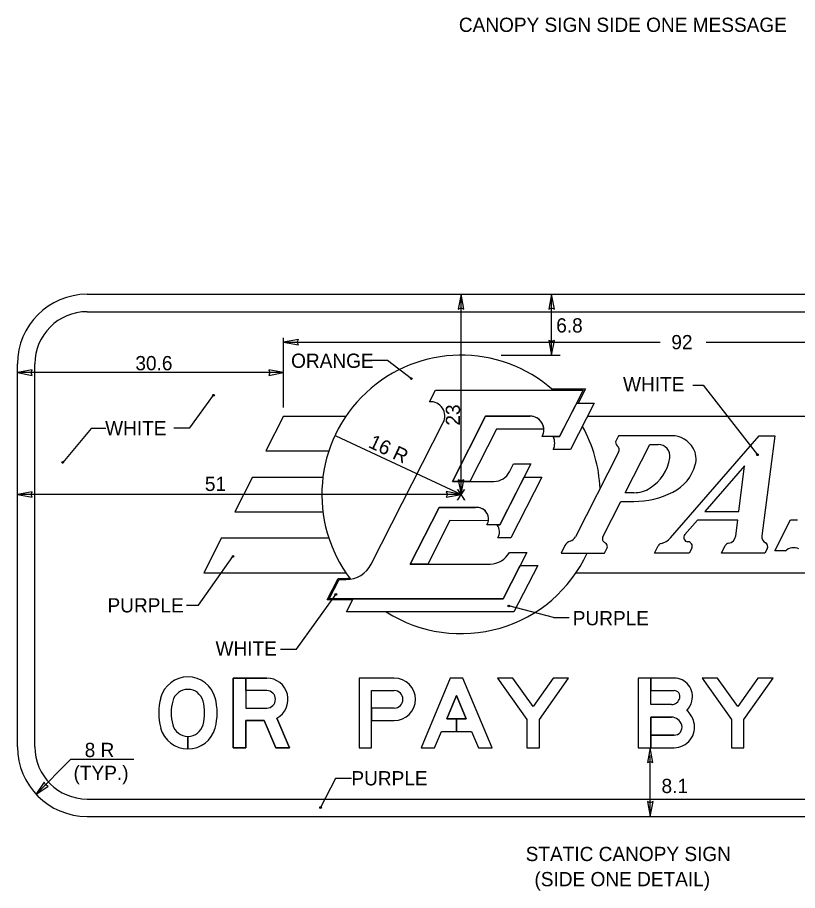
# Model space of a CAD drawing. Extents: x 319706 to 320449, y 1621775 to 1622117.
# Drawn here: x 319821.8 to 319898.5, y 1621852.1 to 1621937.8 of the extents above; entities that cross this region are included whole.
import ezdxf

# ---------------------------------------------------------------- set-up
doc = ezdxf.new("R2010")
doc.units = 0
for name, color, linetype in [('1', 7, 'Continuous'), ('52', 7, 'Continuous'), ('GSBWFill', 7, 'Continuous'), ('GSColorFill', 7, 'Continuous'), ('GSOutline', 7, 'Continuous'), ('SignPanel', 7, 'Continuous')]:
    doc.layers.add(name, color=color, linetype=linetype)

msp = doc.modelspace()

# ---------------------------------------------------------------- linework, layer by layer
at = {"layer": '1'}
for p, q in [((319865.435, 1621890.975), (319865.435, 1621910.64)), ((319874.341, 1621904.654), (319874.341, 1621910.639)), ((319847.993, 1621899.525), (319847.993, 1621906.365)), ((319847.993, 1621905.938), (319884.997, 1621905.938)), ((319889.548, 1621905.938), (319926.653, 1621905.938)), ((319856.646, 1621904.176), (319858.193, 1621904.176)), ((319858.193, 1621904.176), (319860.552, 1621902.355)), ((319869.368, 1621904.654), (319875.196, 1621904.654)), ((319847.993, 1621902.945), (319821.83, 1621902.945)), ((319888.22, 1621901.716), (319889.238, 1621901.716)), ((319889.238, 1621901.716), (319894.572, 1621894.876)), ((319838.762, 1621897.524), (319841.1, 1621900.723)), ((319829.062, 1621897.454), (319826.277, 1621894.117)), ((319830.508, 1621897.454), (319829.062, 1621897.454)), ((319837.215, 1621897.524), (319838.762, 1621897.524)), ((319865.435, 1621890.974), (319853.158, 1621896.699)), ((319850.398, 1621890.975), (319821.83, 1621890.975)), ((319865.435, 1621890.975), (319850.398, 1621890.975)), ((319839.622, 1621880.096), (319843.019, 1621884.886)), ((319849.249, 1621875.759), (319853.128, 1621881.149)), ((319838.436, 1621880.096), (319839.622, 1621880.096)), ((319874.522, 1621878.868), (319870.131, 1621880.017)), ((319874.522, 1621878.868), (319876.07, 1621878.868)), ((319847.701, 1621875.759), (319849.249, 1621875.759)), ((319823.628, 1621861.492), (319827.091, 1621864.955)), ((319827.091, 1621864.955), (319833.282, 1621864.955)), ((319884.034, 1621859.339), (319884.034, 1621865.324)), ((319853.1, 1621863.057), (319851.628, 1621860.204)), ((319854.662, 1621863.057), (319853.1, 1621863.057))]:
    msp.add_line(p, q, dxfattribs=at)
for centre in [(319860.552, 1621902.354), (319841.1, 1621900.722), (319894.571, 1621894.875), (319826.277, 1621894.116), (319843.019, 1621884.884), (319853.128, 1621881.148), (319870.131, 1621880.015), (319870.131, 1621880.015), (319851.628, 1621860.204)]:
    msp.add_circle(centre, 0.0855, dxfattribs=at)
at = {"layer": '52'}
for p, q in [((319865.435, 1621910.64), (319865.155, 1621909.19)), ((319865.705, 1621909.19), (319865.435, 1621910.64)), ((319874.341, 1621910.639), (319874.061, 1621909.189)), ((319874.611, 1621909.189), (319874.341, 1621910.639)), ((319865.155, 1621909.19), (319865.435, 1621909.3)), ((319865.435, 1621909.3), (319865.705, 1621909.19)), ((319874.061, 1621909.189), (319874.341, 1621909.299)), ((319874.341, 1621909.299), (319874.611, 1621909.189)), ((319849.443, 1621906.208), (319847.993, 1621905.938)), ((319847.993, 1621905.938), (319849.443, 1621905.658)), ((319849.333, 1621905.938), (319849.443, 1621906.208)), ((319849.443, 1621905.658), (319849.333, 1621905.938)), ((319874.341, 1621905.994), (319874.071, 1621906.104)), ((319874.071, 1621906.104), (319874.341, 1621904.654)), ((319874.341, 1621904.654), (319874.621, 1621906.104)), ((319874.621, 1621906.104), (319874.341, 1621905.994)), ((319823.28, 1621903.215), (319821.83, 1621902.945)), ((319823.17, 1621902.945), (319823.28, 1621903.215)), ((319847.993, 1621902.945), (319846.543, 1621903.225)), ((319846.543, 1621903.225), (319846.653, 1621902.945)), ((319821.83, 1621902.945), (319823.28, 1621902.665)), ((319823.28, 1621902.665), (319823.17, 1621902.945)), ((319846.653, 1621902.945), (319846.543, 1621902.675)), ((319846.543, 1621902.675), (319847.993, 1621902.945)), ((319865.435, 1621892.315), (319865.165, 1621892.425)), ((319865.165, 1621892.425), (319865.435, 1621890.975)), ((319865.435, 1621890.975), (319865.715, 1621892.425)), ((319865.715, 1621892.425), (319865.435, 1621892.315)), ((319823.28, 1621891.245), (319821.83, 1621890.975)), ((319823.17, 1621890.975), (319823.28, 1621891.245)), ((319865.435, 1621890.975), (319863.985, 1621891.255)), ((319863.985, 1621891.255), (319864.095, 1621890.975)), ((319821.83, 1621890.975), (319823.28, 1621890.695)), ((319823.28, 1621890.695), (319823.17, 1621890.975)), ((319864.095, 1621890.975), (319863.985, 1621890.705)), ((319863.985, 1621890.705), (319865.435, 1621890.975)), ((319884.034, 1621866.088), (319883.754, 1621864.638)), ((319884.304, 1621864.638), (319884.034, 1621866.088)), ((319883.754, 1621864.638), (319884.034, 1621864.748)), ((319884.034, 1621864.748), (319884.304, 1621864.638)), ((319824.463, 1621862.708), (319823.628, 1621861.492)), ((319823.628, 1621861.492), (319824.851, 1621862.32)), ((319824.576, 1621862.44), (319824.463, 1621862.708)), ((319824.851, 1621862.32), (319824.576, 1621862.44)), ((319884.034, 1621860.679), (319883.764, 1621860.789)), ((319883.764, 1621860.789), (319884.034, 1621859.339)), ((319884.034, 1621859.339), (319884.314, 1621860.789)), ((319884.314, 1621860.789), (319884.034, 1621860.679))]:
    msp.add_line(p, q, dxfattribs=at)
at = {"layer": 'GSBWFill'}
for p, q in [((319856.649, 1621871.698), (319858.873, 1621871.698)), ((319838.587, 1621867.199), (319838.587, 1621865.968)), ((319838.588, 1621865.968), (319838.588, 1621867.199))]:
    msp.add_line(p, q, dxfattribs=at)
for points in [[(319847.316, 1621868.997), (319848.576, 1621866.088), (319847.234, 1621866.088), (319846.079, 1621868.756), (319844.266, 1621868.756), (319844.266, 1621866.088), (319843.034, 1621866.088), (319843.034, 1621872.929), (319844.266, 1621872.929), (319844.266, 1621869.987), (319846.342, 1621869.987)], [(319844.266, 1621871.698), (319844.266, 1621872.929), (319846.342, 1621872.929)], [(319858.873, 1621872.929), (319855.418, 1621872.929), (319855.418, 1621866.088), (319856.649, 1621866.088), (319856.649, 1621871.698)], [(319886.111, 1621870.329), (319884.084, 1621870.329), (319884.084, 1621872.929), (319882.852, 1621872.929), (319882.852, 1621866.088), (319884.084, 1621866.088)], [(319886.376, 1621872.929), (319884.084, 1621872.929), (319884.084, 1621871.698), (319886.376, 1621871.698)], [(319846.342, 1621871.698), (319844.266, 1621871.698)], [(319858.873, 1621869.987), (319856.649, 1621869.987), (319856.649, 1621868.756), (319858.873, 1621868.756)], [(319884.084, 1621866.088), (319884.084, 1621869.098), (319886.111, 1621869.098)], [(319886.376, 1621867.319), (319884.084, 1621867.319), (319884.084, 1621866.088), (319886.376, 1621866.088)]]:
    msp.add_lwpolyline(points, dxfattribs=at)
for points in [[(319865.957, 1621868.927), (319864.996, 1621868.927), (319864.996, 1621867.695), (319866.474, 1621867.695), (319867.149, 1621866.088), (319868.485, 1621866.088), (319865.612, 1621872.929), (319864.38, 1621872.929), (319861.507, 1621866.088), (319862.842, 1621866.088), (319863.518, 1621867.695), (319864.996, 1621867.695), (319864.996, 1621868.927), (319864.035, 1621868.927), (319864.996, 1621871.215)], [(319873.137, 1621868.858), (319876.011, 1621872.929), (319874.503, 1621872.929), (319872.522, 1621870.122), (319870.54, 1621872.929), (319869.032, 1621872.929), (319871.906, 1621868.858), (319871.906, 1621866.088), (319873.137, 1621866.088)], [(319893.251, 1621868.858), (319896.125, 1621872.929), (319894.618, 1621872.929), (319892.636, 1621870.122), (319890.654, 1621872.929), (319889.147, 1621872.929), (319892.02, 1621868.858), (319892.02, 1621866.088), (319893.251, 1621866.088)]]:
    msp.add_lwpolyline(points, close=True, dxfattribs=at)
for centre, radius, start, end in [((319838.587, 1621870.276), 2.773, 14.96177, 165.03823), ((319846.342, 1621870.843), 2.087, 297.837, 90), ((319886.376, 1621871.116), 1.813, 345.52249, 90), ((319838.587, 1621870.276), 1.541, 14.96177, 165.03823), ((319846.342, 1621870.843), 0.855, 270, 90), ((319886.376, 1621871.116), 0.582, 345.52249, 90), ((319841.461, 1621869.508), 5.747, 165.03823, 194.96177), ((319841.461, 1621869.508), 4.515, 165.03823, 194.96177), ((319835.714, 1621869.508), 4.515, 345.03823, 14.96177), ((319835.714, 1621869.508), 5.747, 345.03823, 14.96177), ((319886.111, 1621871.185), 0.855, 270, 345.52249), ((319886.111, 1621871.185), 2.087, 316.7114, 345.52249), ((319886.111, 1621868.037), 2.292, 14.47751, 48.4921), ((319886.111, 1621868.037), 1.06, 14.47751, 90), ((319838.587, 1621868.741), 2.773, 194.96177, 270), ((319838.587, 1621868.741), 1.541, 194.96177, 270), ((319838.587, 1621868.741), 1.541, 270.01272, 345.03823), ((319838.587, 1621868.741), 2.773, 270.00707, 345.03823), ((319886.376, 1621868.106), 2.018, 270, 14.47751), ((319886.376, 1621868.106), 0.787, 270, 14.47751)]:
    msp.add_arc(centre, radius, start, end, dxfattribs=at)
for major_axis in [(0, 2.087), (0, 0.855)]:
    msp.add_ellipse((319858.873, 1621870.843), major_axis=major_axis, ratio=0.999994, start_param=3.141593, end_param=6.283185, dxfattribs=at)
at = {"layer": 'GSColorFill'}
for p, q in [((319856.649, 1621871.698), (319858.873, 1621871.698)), ((319838.587, 1621867.199), (319838.587, 1621865.968)), ((319838.588, 1621865.968), (319838.588, 1621867.199))]:
    msp.add_line(p, q, dxfattribs=at)
for points in [[(319847.316, 1621868.997), (319848.576, 1621866.088), (319847.234, 1621866.088), (319846.079, 1621868.756), (319844.266, 1621868.756), (319844.266, 1621866.088), (319843.034, 1621866.088), (319843.034, 1621872.929), (319844.266, 1621872.929), (319844.266, 1621869.987), (319846.342, 1621869.987)], [(319844.266, 1621871.698), (319844.266, 1621872.929), (319846.342, 1621872.929)], [(319858.873, 1621872.929), (319855.418, 1621872.929), (319855.418, 1621866.088), (319856.649, 1621866.088), (319856.649, 1621871.698)], [(319886.111, 1621870.329), (319884.084, 1621870.329), (319884.084, 1621872.929), (319882.852, 1621872.929), (319882.852, 1621866.088), (319884.084, 1621866.088)], [(319886.376, 1621872.929), (319884.084, 1621872.929), (319884.084, 1621871.698), (319886.376, 1621871.698)], [(319846.342, 1621871.698), (319844.266, 1621871.698)], [(319858.873, 1621869.987), (319856.649, 1621869.987), (319856.649, 1621868.756), (319858.873, 1621868.756)], [(319884.084, 1621866.088), (319884.084, 1621869.098), (319886.111, 1621869.098)], [(319886.376, 1621867.319), (319884.084, 1621867.319), (319884.084, 1621866.088), (319886.376, 1621866.088)]]:
    msp.add_lwpolyline(points, dxfattribs=at)
for points in [[(319865.957, 1621868.927), (319864.996, 1621868.927), (319864.996, 1621867.695), (319866.474, 1621867.695), (319867.149, 1621866.088), (319868.485, 1621866.088), (319865.612, 1621872.929), (319864.38, 1621872.929), (319861.507, 1621866.088), (319862.842, 1621866.088), (319863.518, 1621867.695), (319864.996, 1621867.695), (319864.996, 1621868.927), (319864.035, 1621868.927), (319864.996, 1621871.215)], [(319873.137, 1621868.858), (319876.011, 1621872.929), (319874.503, 1621872.929), (319872.522, 1621870.122), (319870.54, 1621872.929), (319869.032, 1621872.929), (319871.906, 1621868.858), (319871.906, 1621866.088), (319873.137, 1621866.088)], [(319893.251, 1621868.858), (319896.125, 1621872.929), (319894.618, 1621872.929), (319892.636, 1621870.122), (319890.654, 1621872.929), (319889.147, 1621872.929), (319892.02, 1621868.858), (319892.02, 1621866.088), (319893.251, 1621866.088)]]:
    msp.add_lwpolyline(points, close=True, dxfattribs=at)
for centre, radius, start, end in [((319838.587, 1621870.276), 2.773, 14.96177, 165.03823), ((319846.342, 1621870.843), 2.087, 297.837, 90), ((319886.376, 1621871.116), 1.813, 345.52249, 90), ((319838.587, 1621870.276), 1.541, 14.96177, 165.03823), ((319846.342, 1621870.843), 0.855, 270, 90), ((319886.376, 1621871.116), 0.582, 345.52249, 90), ((319841.461, 1621869.508), 5.747, 165.03823, 194.96177), ((319841.461, 1621869.508), 4.515, 165.03823, 194.96177), ((319835.714, 1621869.508), 4.515, 345.03823, 14.96177), ((319835.714, 1621869.508), 5.747, 345.03823, 14.96177), ((319886.111, 1621871.185), 0.855, 270, 345.52249), ((319886.111, 1621871.185), 2.087, 316.7114, 345.52249), ((319886.111, 1621868.037), 2.292, 14.47751, 48.4921), ((319886.111, 1621868.037), 1.06, 14.47751, 90), ((319838.587, 1621868.741), 2.773, 194.96177, 270), ((319838.587, 1621868.741), 1.541, 194.96177, 270), ((319838.587, 1621868.741), 1.541, 270.01272, 345.03823), ((319838.587, 1621868.741), 2.773, 270.00707, 345.03823), ((319886.376, 1621868.106), 2.018, 270, 14.47751), ((319886.376, 1621868.106), 0.787, 270, 14.47751)]:
    msp.add_arc(centre, radius, start, end, dxfattribs=at)
for major_axis in [(0, 2.087), (0, 0.855)]:
    msp.add_ellipse((319858.873, 1621870.843), major_axis=major_axis, ratio=0.999994, start_param=3.141593, end_param=6.283185, dxfattribs=at)
at = {"layer": 'GSOutline'}
for p, q in [((319856.649, 1621871.698), (319858.873, 1621871.698)), ((319856.649, 1621868.756), (319858.873, 1621868.756)), ((319882.852, 1621866.088), (319886.376, 1621866.088))]:
    msp.add_line(p, q, dxfattribs=at)
for points in [[(319846.342, 1621872.929), (319843.034, 1621872.929), (319843.034, 1621866.088), (319844.266, 1621866.088), (319844.266, 1621868.756), (319846.079, 1621868.756), (319847.234, 1621866.088), (319848.576, 1621866.088), (319847.316, 1621868.997)], [(319858.873, 1621872.929), (319855.418, 1621872.929), (319855.418, 1621866.088), (319856.649, 1621866.088), (319856.649, 1621868.756)], [(319886.376, 1621872.929), (319882.852, 1621872.929), (319882.852, 1621866.088)], [(319846.342, 1621871.698), (319844.266, 1621871.698), (319844.266, 1621869.987), (319846.342, 1621869.987)], [(319858.873, 1621869.987), (319856.649, 1621869.987), (319856.649, 1621871.698)], [(319886.111, 1621870.329), (319884.084, 1621870.329), (319884.084, 1621871.698), (319886.376, 1621871.698)], [(319886.111, 1621869.098), (319884.084, 1621869.098), (319884.084, 1621867.319), (319886.376, 1621867.319)]]:
    msp.add_lwpolyline(points, dxfattribs=at)
for points in [[(319863.518, 1621867.695), (319866.474, 1621867.695), (319867.149, 1621866.088), (319868.485, 1621866.088), (319865.612, 1621872.929), (319864.38, 1621872.929), (319861.507, 1621866.088), (319862.842, 1621866.088)], [(319873.137, 1621868.858), (319876.011, 1621872.929), (319874.503, 1621872.929), (319872.522, 1621870.122), (319870.54, 1621872.929), (319869.032, 1621872.929), (319871.906, 1621868.858), (319871.906, 1621866.088), (319873.137, 1621866.088)], [(319893.251, 1621868.858), (319896.125, 1621872.929), (319894.618, 1621872.929), (319892.636, 1621870.122), (319890.654, 1621872.929), (319889.147, 1621872.929), (319892.02, 1621868.858), (319892.02, 1621866.088), (319893.251, 1621866.088)], [(319865.957, 1621868.927), (319864.996, 1621871.215), (319864.035, 1621868.927)]]:
    msp.add_lwpolyline(points, close=True, dxfattribs=at)
for centre, radius, start, end in [((319838.587, 1621870.276), 2.773, 14.96177, 165.03823), ((319846.342, 1621870.843), 2.087, 297.837, 90), ((319886.376, 1621871.116), 1.813, 345.52249, 90), ((319838.587, 1621870.276), 1.541, 14.96177, 165.03823), ((319846.342, 1621870.843), 0.855, 270, 90), ((319886.376, 1621871.116), 0.582, 345.52249, 90), ((319841.461, 1621869.508), 5.747, 165.03823, 194.96177), ((319841.461, 1621869.508), 4.515, 165.03823, 194.96177), ((319835.714, 1621869.508), 4.515, 345.03823, 14.96177), ((319835.714, 1621869.508), 5.747, 345.03823, 14.96177), ((319886.111, 1621871.185), 0.855, 270, 345.52249), ((319886.111, 1621871.185), 2.087, 316.7114, 345.52249), ((319886.111, 1621868.037), 2.292, 14.47751, 48.4921), ((319886.111, 1621868.037), 1.06, 14.47751, 90), ((319838.587, 1621868.741), 2.773, 194.96177, 345.03823), ((319838.587, 1621868.741), 1.541, 194.96177, 345.03823), ((319886.376, 1621868.106), 2.018, 270, 14.47751), ((319886.376, 1621868.106), 0.787, 270, 14.47751)]:
    msp.add_arc(centre, radius, start, end, dxfattribs=at)
for major_axis in [(0, 2.087), (0, 0.855)]:
    msp.add_ellipse((319858.873, 1621870.843), major_axis=major_axis, ratio=0.999994, start_param=3.141593, end_param=6.283185, dxfattribs=at)
at = {"layer": 'SignPanel'}
for p, q in [((319828.67, 1621910.639), (319938.11, 1621910.639)), ((319828.67, 1621908.929), (319938.11, 1621908.929)), ((319821.83, 1621866.179), (319821.83, 1621903.799)), ((319823.54, 1621866.179), (319823.54, 1621903.799)), ((319862.341, 1621900.087), (319862.924, 1621901.234)), ((319862.924, 1621901.234), (319877.459, 1621901.234)), ((319874.335, 1621901.362), (319877.668, 1621901.362)), ((319877.459, 1621901.234), (319875.131, 1621896.663)), ((319877.668, 1621901.362), (319876.949, 1621899.952)), ((319875.128, 1621896.658), (319876.807, 1621899.952)), ((319875.128, 1621896.658), (319876.807, 1621899.952)), ((319878.534, 1621899.952), (319876.204, 1621895.38)), ((319878.534, 1621899.952), (319876.204, 1621895.38)), ((319876.807, 1621899.952), (319878.534, 1621899.952)), ((319876.807, 1621899.952), (319878.534, 1621899.952)), ((319847.993, 1621898.669), (319846.252, 1621895.249)), ((319847.993, 1621898.669), (319854.124, 1621898.669)), ((319856.596, 1621884.112), (319863.692, 1621898.04)), ((319867.85, 1621898.669), (319864.583, 1621892.257)), ((319864.583, 1621892.257), (319867.85, 1621898.669)), ((319864.583, 1621892.257), (319867.85, 1621898.669)), ((319872.208, 1621898.669), (319867.85, 1621898.669)), ((319867.85, 1621898.669), (319872.208, 1621898.669)), ((319867.85, 1621898.669), (319872.208, 1621898.669)), ((319877.879, 1621898.669), (319926.653, 1621898.669)), ((319868.924, 1621897.387), (319866.31, 1621892.257)), ((319868.924, 1621897.387), (319866.31, 1621892.257)), ((319873.575, 1621897.387), (319868.924, 1621897.387)), ((319873.575, 1621897.387), (319868.924, 1621897.387)), ((319875.131, 1621896.663), (319873.42, 1621896.663)), ((319874.492, 1621896.658), (319875.128, 1621896.658)), ((319874.492, 1621896.658), (319875.128, 1621896.658)), ((319880.91, 1621896.745), (319880.677, 1621896.289)), ((319886.146, 1621896.745), (319880.91, 1621896.745)), ((319886.015, 1621886.704), (319894.746, 1621896.745)), ((319894.746, 1621896.745), (319896.285, 1621896.745)), ((319896.285, 1621896.745), (319895.005, 1621886.906)), ((319876.204, 1621895.38), (319874.494, 1621895.38)), ((319876.204, 1621895.38), (319874.494, 1621895.38)), ((319881.581, 1621891.145), (319884, 1621895.89)), ((319884, 1621895.89), (319884.824, 1621895.89)), ((319846.252, 1621895.249), (319852.44, 1621895.249)), ((319880.925, 1621895.129), (319876.691, 1621886.821)), ((319872.303, 1621893.967), (319869.254, 1621887.982)), ((319870.197, 1621893.19), (319870.593, 1621893.967)), ((319870.593, 1621893.967), (319872.303, 1621893.967)), ((319893.314, 1621893.796), (319889.411, 1621889.306)), ((319892.73, 1621889.306), (319893.314, 1621893.796)), ((319844.947, 1621892.684), (319843.206, 1621889.264)), ((319844.947, 1621892.684), (319851.861, 1621892.684)), ((319864.583, 1621892.257), (319868.674, 1621892.257)), ((319866.31, 1621892.257), (319864.583, 1621892.257)), ((319866.31, 1621892.257), (319864.583, 1621892.257)), ((319869.254, 1621887.982), (319871.65, 1621892.684)), ((319869.254, 1621887.982), (319871.65, 1621892.684)), ((319873.377, 1621892.684), (319870.327, 1621886.699)), ((319873.377, 1621892.684), (319870.327, 1621886.699)), ((319871.65, 1621892.684), (319873.377, 1621892.684)), ((319871.65, 1621892.684), (319873.377, 1621892.684)), ((319882.428, 1621891.145), (319881.581, 1621891.145)), ((319879.377, 1621886.821), (319881.145, 1621890.29)), ((319881.145, 1621890.29), (319882.428, 1621890.29)), ((319863.277, 1621889.692), (319860.445, 1621884.134)), ((319860.445, 1621884.134), (319863.277, 1621889.692)), ((319860.445, 1621884.134), (319863.277, 1621889.692)), ((319867.029, 1621889.692), (319863.277, 1621889.692)), ((319863.277, 1621889.692), (319866.868, 1621889.68)), ((319863.277, 1621889.692), (319866.868, 1621889.68)), ((319843.206, 1621889.264), (319851.861, 1621889.264)), ((319889.411, 1621889.306), (319892.73, 1621889.306)), ((319864.349, 1621888.406), (319862.172, 1621884.134)), ((319864.349, 1621888.406), (319862.172, 1621884.134)), ((319868.124, 1621888.394), (319864.349, 1621888.406)), ((319868.124, 1621888.394), (319864.349, 1621888.406)), ((319869.254, 1621887.982), (319867.966, 1621887.982)), ((319868.985, 1621887.982), (319869.254, 1621887.982)), ((319868.985, 1621887.982), (319869.254, 1621887.982)), ((319888.67, 1621888.451), (319887.43, 1621887.027)), ((319892.643, 1621888.451), (319888.67, 1621888.451)), ((319892.44, 1621886.906), (319892.643, 1621888.451)), ((319896.279, 1621885.417), (319897.831, 1621888.464)), ((319897.831, 1621888.464), (319898.518, 1621888.464)), ((319841.9, 1621886.699), (319840.159, 1621883.279)), ((319841.9, 1621886.699), (319852.44, 1621886.699)), ((319870.327, 1621886.699), (319869.045, 1621886.699)), ((319870.327, 1621886.699), (319869.045, 1621886.699)), ((319875.652, 1621885.957), (319875.268, 1621885.202)), ((319884.442, 1621885.202), (319884.814, 1621885.934)), ((319891.04, 1621885.202), (319891.418, 1621885.945)), ((319871.899, 1621885.285), (319869.57, 1621880.714)), ((319870.188, 1621885.285), (319871.899, 1621885.285)), ((319875.268, 1621885.202), (319879.543, 1621885.202)), ((319879.543, 1621885.202), (319879.775, 1621885.66)), ((319887.862, 1621885.202), (319884.442, 1621885.202)), ((319888.114, 1621885.696), (319887.862, 1621885.202)), ((319895.315, 1621885.202), (319891.04, 1621885.202)), ((319895.54, 1621885.643), (319895.315, 1621885.202)), ((319897.318, 1621885.417), (319896.279, 1621885.417)), ((319860.445, 1621884.134), (319868.292, 1621884.134)), ((319862.172, 1621884.134), (319860.445, 1621884.134)), ((319862.172, 1621884.134), (319860.445, 1621884.134)), ((319869.57, 1621880.714), (319871.245, 1621884.003)), ((319869.57, 1621880.714), (319871.245, 1621884.003)), ((319872.973, 1621884.003), (319870.643, 1621879.432)), ((319872.973, 1621884.003), (319870.643, 1621879.432)), ((319871.245, 1621884.003), (319872.973, 1621884.003)), ((319871.245, 1621884.003), (319872.973, 1621884.003)), ((319840.159, 1621883.279), (319854.124, 1621883.279)), ((319852.287, 1621880.602), (319853.371, 1621882.73)), ((319852.47, 1621880.714), (319853.44, 1621882.618)), ((319853.371, 1621882.73), (319854.158, 1621882.73)), ((319853.44, 1621882.618), (319854.158, 1621882.618)), ((319876.745, 1621883.279), (319918.811, 1621883.279)), ((319854.776, 1621880.602), (319852.287, 1621880.602)), ((319869.57, 1621880.714), (319852.47, 1621880.714)), ((319854.18, 1621879.432), (319854.833, 1621880.714)), ((319854.18, 1621879.432), (319854.833, 1621880.714)), ((319854.833, 1621880.714), (319869.57, 1621880.714)), ((319854.833, 1621880.714), (319869.57, 1621880.714)), ((319870.643, 1621879.432), (319854.18, 1621879.432)), ((319870.643, 1621879.432), (319854.18, 1621879.432)), ((319828.67, 1621861.049), (319938.11, 1621861.049)), ((319828.67, 1621859.339), (319938.11, 1621859.339))]:
    msp.add_line(p, q, dxfattribs=at)
for centre, radius, start, end in [((319828.67, 1621903.798), 6.84, 90, 180), ((319828.67, 1621903.798), 5.13, 90, 180), ((319865.435, 1621890.973), 13.68, 48.59038, 217.4727), ((319862.434, 1621898.679), 1.411, 332.99985, 93.80449), ((319872.209, 1621897.3), 1.368, 332.20885, 90), ((319872.209, 1621897.3), 1.368, 3.58332, 90), ((319872.209, 1621897.3), 1.368, 3.58332, 90), ((319865.435, 1621890.973), 13.68, 2.42356, 29.27706), ((319873.283, 1621896.017), 1.368, 332.20885, 27.91266), ((319873.283, 1621896.017), 1.368, 332.20885, 27.91266), ((319881.057, 1621896.094), 0.428, 152.97842, 231.16017), ((319886.146, 1621894.307), 2.437, 29.43149, 90), ((319880.468, 1621895.361), 0.513, 333.00266, 51.16017), ((319884.823, 1621894.735), 1.154, 351.07601, 90), ((319886.407, 1621894.454), 2.138, 344.70738, 29.43149), ((319881.74, 1621895.219), 4.275, 302.42062, 351.07601), ((319884.345, 1621895.018), 4.275, 296.64315, 344.70738), ((319868.674, 1621893.965), 1.71, 270, 332.98829), ((319882.428, 1621894.136), 2.993, 270, 302.42062), ((319882.428, 1621898.839), 8.55, 270, 296.64315), ((319867.029, 1621888.579), 1.111, 350.35016, 98.33436), ((319867.029, 1621888.579), 1.111, 350.35016, 98.33436), ((319867.029, 1621888.579), 1.111, 327.42103, 90), ((319868.109, 1621887.296), 1.111, 327.42103, 37.97987), ((319868.109, 1621887.296), 1.111, 327.42103, 37.97987), ((319875.93, 1621887.208), 0.855, 286.43167, 332.99588), ((319879.758, 1621886.626), 0.427, 152.98839, 244.78323), ((319887.753, 1621886.745), 0.427, 138.98241, 268.68694), ((319891.593, 1621887.016), 0.855, 279.2397, 352.56317), ((319895.683, 1621886.817), 0.684, 172.58839, 241.86732), ((319876.414, 1621885.567), 0.855, 106.43168, 152.97425), ((319879.394, 1621885.853), 0.427, 333.02391, 64.78322), ((319885.195, 1621885.739), 0.427, 102.71621, 153.02391), ((319884.725, 1621887.824), 1.71, 282.71621, 318.99659), ((319887.733, 1621885.89), 0.427, 332.97842, 88.68694), ((319891.799, 1621885.75), 0.428, 99.2397, 153.02391), ((319895.159, 1621885.836), 0.427, 332.97842, 61.86732), ((319865.435, 1621890.973), 13.68, 237.53826, 335.04698), ((319868.292, 1621886.27), 2.138, 270, 332.5096), ((319898.137, 1621884.543), 1.197, 64.37946, 133.18921), ((319854.158, 1621885.354), 2.736, 270, 332.99913), ((319854.158, 1621885.354), 2.625, 270, 277.50379), ((319828.67, 1621866.178), 6.84, 180, 270), ((319828.67, 1621866.178), 5.13, 180, 270)]:
    msp.add_arc(centre, radius, start, end, dxfattribs=at)

# ---------------------------------------------------------------- texts
at = {"layer": '1'}
for s, p in [('CANOPY SIGN SIDE ONE MESSAGE', (319865.222, 1621936.418)), ('6.8', (319874.795, 1621906.884)), ('92', (319886.109, 1621905.237)), ('ORANGE', (319848.731, 1621903.41)), ('30.6', (319833.422, 1621903.175)), ('WHITE', (319881.364, 1621901.098)), ('WHITE', (319830.45, 1621896.795)), ('51', (319840.256, 1621891.312)), ('x', (319864.974, 1621890.402)), ('PURPLE', (319830.682, 1621879.379)), ('PURPLE', (319876.42, 1621878.115)), ('WHITE', (319841.303, 1621875.147)), ('8 R', (319828.439, 1621865.169)), ('(TYP.)', (319827.343, 1621862.914)), ('PURPLE', (319854.658, 1621862.385)), ('8.1', (319885.146, 1621861.632)), ('STATIC CANOPY SIGN', (319871.791, 1621854.95)), ('(SIDE ONE DETAIL)', (319872.655, 1621852.476))]:
    msp.add_text(s, height=1.4, dxfattribs=at).set_placement(p)
for s, rotation, p in [('23', 90, (319865.338, 1621897.733)), ('16 R', 334.99906, (319856.242, 1621895.645))]:
    msp.add_text(s, height=1.4, rotation=rotation, dxfattribs=at).set_placement(p)

doc.saveas('drawing.dxf')
